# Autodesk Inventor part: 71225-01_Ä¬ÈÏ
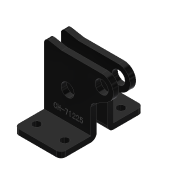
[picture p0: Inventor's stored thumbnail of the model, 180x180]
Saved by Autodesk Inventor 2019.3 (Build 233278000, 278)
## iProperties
Created: 2010-06
Part Number: 71225-01_Ä¬ÈÏ
Material: Ogólny
Document SubType Name: Modeling
Designer: CADENGINEERING4
Density: 1 g/cm^3
Appearance: Gładki — czarny
Author: CADENGINEERING4
Revision Number: ÈÎºÎ
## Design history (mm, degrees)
feature "NONE"
feature "NONE:1"
node "Bryła1"
node "Bryła2"
